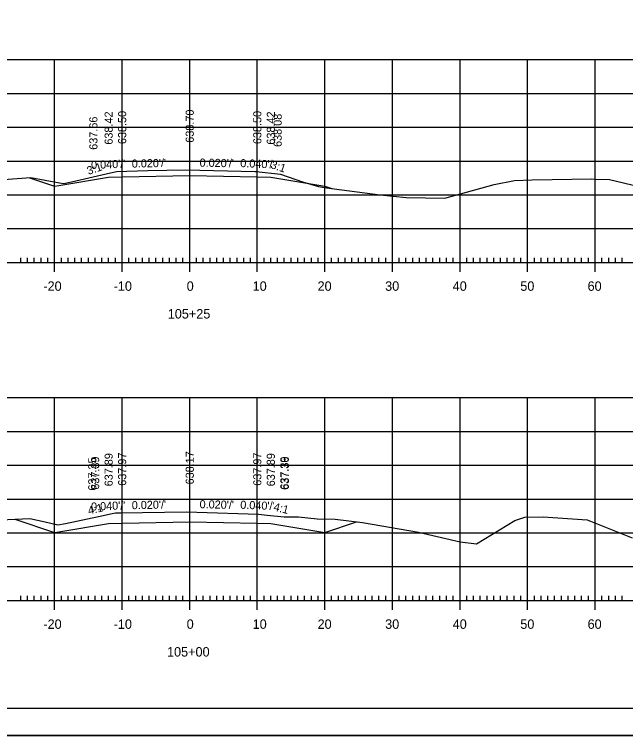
# Model space of a CAD drawing. Extents: x 1381471 to 1382703, y 370300 to 371487.
# Drawn here: x 1382110.7 to 1382201.1, y 371273.8 to 371380.5 of the extents above; entities that cross this region are included whole.
import ezdxf

# ---------------------------------------------------------------- set-up
doc = ezdxf.new("R2010")
doc.units = 0
doc.layers.add('Level 26', color=7, linetype='Continuous')
doc.layers.add('Level 45', color=7, linetype='Continuous')

msp = doc.modelspace()

# ---------------------------------------------------------------- linework, layer by layer
at = {"layer": 'Level 26'}
for points in [[(1382112.91, 371356.32), (1382116.61, 371355.09), (1382117.23, 371355.19), (1382124.61, 371356.42), (1382126.61, 371356.46), (1382136.61, 371356.66), (1382146.61, 371356.46), (1382148.61, 371356.42), (1382156, 371355.19), (1382156.61, 371355.09), (1382157.66, 371354.74)], [(1382110.71, 371305.84), (1382116.61, 371303.87), (1382117.23, 371303.97), (1382124.61, 371305.2), (1382126.61, 371305.24), (1382136.61, 371305.44), (1382146.61, 371305.24), (1382148.61, 371305.2), (1382156, 371303.97), (1382156.61, 371303.87), (1382161.27, 371305.42)]]:
    msp.add_lwpolyline(points, dxfattribs=at)
at = {"layer": 'Level 45'}
for p, q in [((1381996.61, 371373.8), (1382276.61, 371373.8)), ((1382116.61, 371343.8), (1382116.61, 371373.8)), ((1382126.61, 371343.8), (1382126.61, 371373.8)), ((1382136.61, 371343.8), (1382136.61, 371373.8)), ((1382146.61, 371343.8), (1382146.61, 371373.8)), ((1382156.61, 371343.8), (1382156.61, 371373.8)), ((1382166.61, 371343.8), (1382166.61, 371373.8)), ((1382176.61, 371343.8), (1382176.61, 371373.8)), ((1382186.61, 371343.8), (1382186.61, 371373.8)), ((1382196.61, 371343.8), (1382196.61, 371373.8)), ((1381996.61, 371368.8), (1382276.61, 371368.8)), ((1381996.61, 371363.8), (1382276.61, 371363.8)), ((1381996.61, 371358.8), (1382276.61, 371358.8)), ((1381996.61, 371353.8), (1382276.61, 371353.8)), ((1381996.61, 371348.8), (1382276.61, 371348.8)), ((1382116.61, 371342.4), (1382116.61, 371345.2)), ((1382126.61, 371342.4), (1382126.61, 371345.2)), ((1382136.61, 371342.4), (1382136.61, 371345.2)), ((1382146.61, 371342.4), (1382146.61, 371345.2)), ((1382156.61, 371342.4), (1382156.61, 371345.2)), ((1382166.61, 371342.4), (1382166.61, 371345.2)), ((1382176.61, 371342.4), (1382176.61, 371345.2)), ((1382186.61, 371342.4), (1382186.61, 371345.2)), ((1382196.61, 371342.4), (1382196.61, 371345.2)), ((1382111.61, 371343.8), (1382111.61, 371344.5)), ((1382112.61, 371343.8), (1382112.61, 371344.5)), ((1382113.61, 371343.8), (1382113.61, 371344.5)), ((1382114.61, 371343.8), (1382114.61, 371344.5)), ((1382115.61, 371343.8), (1382115.61, 371344.5)), ((1382117.61, 371343.8), (1382117.61, 371344.5)), ((1382118.61, 371343.8), (1382118.61, 371344.5)), ((1382119.61, 371343.8), (1382119.61, 371344.5)), ((1382120.61, 371343.8), (1382120.61, 371344.5)), ((1382121.61, 371343.8), (1382121.61, 371344.5)), ((1382122.61, 371343.8), (1382122.61, 371344.5)), ((1382123.61, 371343.8), (1382123.61, 371344.5)), ((1382124.61, 371343.8), (1382124.61, 371344.5)), ((1382125.61, 371343.8), (1382125.61, 371344.5)), ((1382127.61, 371343.8), (1382127.61, 371344.5)), ((1382128.61, 371343.8), (1382128.61, 371344.5)), ((1382129.61, 371343.8), (1382129.61, 371344.5)), ((1382130.61, 371343.8), (1382130.61, 371344.5)), ((1382131.61, 371343.8), (1382131.61, 371344.5)), ((1382132.61, 371343.8), (1382132.61, 371344.5)), ((1382133.61, 371343.8), (1382133.61, 371344.5)), ((1382134.61, 371343.8), (1382134.61, 371344.5)), ((1382135.61, 371343.8), (1382135.61, 371344.5)), ((1382137.61, 371343.8), (1382137.61, 371344.5)), ((1382138.61, 371343.8), (1382138.61, 371344.5)), ((1382139.61, 371343.8), (1382139.61, 371344.5)), ((1382140.61, 371343.8), (1382140.61, 371344.5)), ((1382141.61, 371343.8), (1382141.61, 371344.5)), ((1382142.61, 371343.8), (1382142.61, 371344.5)), ((1382143.61, 371343.8), (1382143.61, 371344.5)), ((1382144.61, 371343.8), (1382144.61, 371344.5)), ((1382145.61, 371343.8), (1382145.61, 371344.5)), ((1382147.61, 371343.8), (1382147.61, 371344.5)), ((1382148.61, 371343.8), (1382148.61, 371344.5)), ((1382149.61, 371343.8), (1382149.61, 371344.5)), ((1382150.61, 371343.8), (1382150.61, 371344.5)), ((1382151.61, 371343.8), (1382151.61, 371344.5)), ((1382152.61, 371343.8), (1382152.61, 371344.5)), ((1382153.61, 371343.8), (1382153.61, 371344.5)), ((1382154.61, 371343.8), (1382154.61, 371344.5)), ((1382155.61, 371343.8), (1382155.61, 371344.5)), ((1382157.61, 371343.8), (1382157.61, 371344.5)), ((1382158.61, 371343.8), (1382158.61, 371344.5)), ((1382159.61, 371343.8), (1382159.61, 371344.5)), ((1382160.61, 371343.8), (1382160.61, 371344.5)), ((1382161.61, 371343.8), (1382161.61, 371344.5)), ((1382162.61, 371343.8), (1382162.61, 371344.5)), ((1382163.61, 371343.8), (1382163.61, 371344.5)), ((1382164.61, 371343.8), (1382164.61, 371344.5)), ((1382165.61, 371343.8), (1382165.61, 371344.5)), ((1382167.61, 371343.8), (1382167.61, 371344.5)), ((1382168.61, 371343.8), (1382168.61, 371344.5)), ((1382169.61, 371343.8), (1382169.61, 371344.5)), ((1382170.61, 371343.8), (1382170.61, 371344.5)), ((1382171.61, 371343.8), (1382171.61, 371344.5)), ((1382172.61, 371343.8), (1382172.61, 371344.5)), ((1382173.61, 371343.8), (1382173.61, 371344.5)), ((1382174.61, 371343.8), (1382174.61, 371344.5)), ((1382175.61, 371343.8), (1382175.61, 371344.5)), ((1382177.61, 371343.8), (1382177.61, 371344.5)), ((1382178.61, 371343.8), (1382178.61, 371344.5)), ((1382179.61, 371343.8), (1382179.61, 371344.5)), ((1382180.61, 371343.8), (1382180.61, 371344.5)), ((1382181.61, 371343.8), (1382181.61, 371344.5)), ((1382182.61, 371343.8), (1382182.61, 371344.5)), ((1382183.61, 371343.8), (1382183.61, 371344.5)), ((1382184.61, 371343.8), (1382184.61, 371344.5)), ((1382185.61, 371343.8), (1382185.61, 371344.5)), ((1382187.61, 371343.8), (1382187.61, 371344.5)), ((1382188.61, 371343.8), (1382188.61, 371344.5)), ((1382189.61, 371343.8), (1382189.61, 371344.5)), ((1382190.61, 371343.8), (1382190.61, 371344.5)), ((1382191.61, 371343.8), (1382191.61, 371344.5)), ((1382192.61, 371343.8), (1382192.61, 371344.5)), ((1382193.61, 371343.8), (1382193.61, 371344.5)), ((1382194.61, 371343.8), (1382194.61, 371344.5)), ((1382195.61, 371343.8), (1382195.61, 371344.5)), ((1382197.61, 371343.8), (1382197.61, 371344.5)), ((1382198.61, 371343.8), (1382198.61, 371344.5)), ((1382199.61, 371343.8), (1382199.61, 371344.5)), ((1382200.61, 371343.8), (1382200.61, 371344.5)), ((1381996.61, 371343.8), (1382276.61, 371343.8)), ((1381996.61, 371343.8), (1382276.61, 371343.8)), ((1381996.61, 371323.8), (1382276.61, 371323.8)), ((1382116.61, 371293.8), (1382116.61, 371323.8)), ((1382126.61, 371293.8), (1382126.61, 371323.8)), ((1382136.61, 371293.8), (1382136.61, 371323.8)), ((1382146.61, 371293.8), (1382146.61, 371323.8)), ((1382156.61, 371293.8), (1382156.61, 371323.8)), ((1382166.61, 371293.8), (1382166.61, 371323.8)), ((1382176.61, 371293.8), (1382176.61, 371323.8)), ((1382186.61, 371293.8), (1382186.61, 371323.8)), ((1382196.61, 371293.8), (1382196.61, 371323.8)), ((1381996.61, 371318.8), (1382276.61, 371318.8)), ((1381996.61, 371313.8), (1382276.61, 371313.8)), ((1381996.61, 371308.8), (1382276.61, 371308.8)), ((1381996.61, 371303.8), (1382276.61, 371303.8)), ((1381996.61, 371298.8), (1382276.61, 371298.8)), ((1382116.61, 371292.4), (1382116.61, 371295.2)), ((1382126.61, 371292.4), (1382126.61, 371295.2)), ((1382136.61, 371292.4), (1382136.61, 371295.2)), ((1382146.61, 371292.4), (1382146.61, 371295.2)), ((1382156.61, 371292.4), (1382156.61, 371295.2)), ((1382166.61, 371292.4), (1382166.61, 371295.2)), ((1382176.61, 371292.4), (1382176.61, 371295.2)), ((1382186.61, 371292.4), (1382186.61, 371295.2)), ((1382196.61, 371292.4), (1382196.61, 371295.2)), ((1382111.61, 371293.8), (1382111.61, 371294.5)), ((1382112.61, 371293.8), (1382112.61, 371294.5)), ((1382113.61, 371293.8), (1382113.61, 371294.5)), ((1382114.61, 371293.8), (1382114.61, 371294.5)), ((1382115.61, 371293.8), (1382115.61, 371294.5)), ((1382117.61, 371293.8), (1382117.61, 371294.5)), ((1382118.61, 371293.8), (1382118.61, 371294.5)), ((1382119.61, 371293.8), (1382119.61, 371294.5)), ((1382120.61, 371293.8), (1382120.61, 371294.5)), ((1382121.61, 371293.8), (1382121.61, 371294.5)), ((1382122.61, 371293.8), (1382122.61, 371294.5)), ((1382123.61, 371293.8), (1382123.61, 371294.5)), ((1382124.61, 371293.8), (1382124.61, 371294.5)), ((1382125.61, 371293.8), (1382125.61, 371294.5)), ((1382127.61, 371293.8), (1382127.61, 371294.5)), ((1382128.61, 371293.8), (1382128.61, 371294.5)), ((1382129.61, 371293.8), (1382129.61, 371294.5)), ((1382130.61, 371293.8), (1382130.61, 371294.5)), ((1382131.61, 371293.8), (1382131.61, 371294.5)), ((1382132.61, 371293.8), (1382132.61, 371294.5)), ((1382133.61, 371293.8), (1382133.61, 371294.5)), ((1382134.61, 371293.8), (1382134.61, 371294.5)), ((1382135.61, 371293.8), (1382135.61, 371294.5)), ((1382137.61, 371293.8), (1382137.61, 371294.5)), ((1382138.61, 371293.8), (1382138.61, 371294.5)), ((1382139.61, 371293.8), (1382139.61, 371294.5)), ((1382140.61, 371293.8), (1382140.61, 371294.5)), ((1382141.61, 371293.8), (1382141.61, 371294.5)), ((1382142.61, 371293.8), (1382142.61, 371294.5)), ((1382143.61, 371293.8), (1382143.61, 371294.5)), ((1382144.61, 371293.8), (1382144.61, 371294.5)), ((1382145.61, 371293.8), (1382145.61, 371294.5)), ((1382147.61, 371293.8), (1382147.61, 371294.5)), ((1382148.61, 371293.8), (1382148.61, 371294.5)), ((1382149.61, 371293.8), (1382149.61, 371294.5)), ((1382150.61, 371293.8), (1382150.61, 371294.5)), ((1382151.61, 371293.8), (1382151.61, 371294.5)), ((1382152.61, 371293.8), (1382152.61, 371294.5)), ((1382153.61, 371293.8), (1382153.61, 371294.5)), ((1382154.61, 371293.8), (1382154.61, 371294.5)), ((1382155.61, 371293.8), (1382155.61, 371294.5)), ((1382157.61, 371293.8), (1382157.61, 371294.5)), ((1382158.61, 371293.8), (1382158.61, 371294.5)), ((1382159.61, 371293.8), (1382159.61, 371294.5)), ((1382160.61, 371293.8), (1382160.61, 371294.5)), ((1382161.61, 371293.8), (1382161.61, 371294.5)), ((1382162.61, 371293.8), (1382162.61, 371294.5)), ((1382163.61, 371293.8), (1382163.61, 371294.5)), ((1382164.61, 371293.8), (1382164.61, 371294.5)), ((1382165.61, 371293.8), (1382165.61, 371294.5)), ((1382167.61, 371293.8), (1382167.61, 371294.5)), ((1382168.61, 371293.8), (1382168.61, 371294.5)), ((1382169.61, 371293.8), (1382169.61, 371294.5)), ((1382170.61, 371293.8), (1382170.61, 371294.5)), ((1382171.61, 371293.8), (1382171.61, 371294.5)), ((1382172.61, 371293.8), (1382172.61, 371294.5)), ((1382173.61, 371293.8), (1382173.61, 371294.5)), ((1382174.61, 371293.8), (1382174.61, 371294.5)), ((1382175.61, 371293.8), (1382175.61, 371294.5)), ((1382177.61, 371293.8), (1382177.61, 371294.5)), ((1382178.61, 371293.8), (1382178.61, 371294.5)), ((1382179.61, 371293.8), (1382179.61, 371294.5)), ((1382180.61, 371293.8), (1382180.61, 371294.5)), ((1382181.61, 371293.8), (1382181.61, 371294.5)), ((1382182.61, 371293.8), (1382182.61, 371294.5)), ((1382183.61, 371293.8), (1382183.61, 371294.5)), ((1382184.61, 371293.8), (1382184.61, 371294.5)), ((1382185.61, 371293.8), (1382185.61, 371294.5)), ((1382187.61, 371293.8), (1382187.61, 371294.5)), ((1382188.61, 371293.8), (1382188.61, 371294.5)), ((1382189.61, 371293.8), (1382189.61, 371294.5)), ((1382190.61, 371293.8), (1382190.61, 371294.5)), ((1382191.61, 371293.8), (1382191.61, 371294.5)), ((1382192.61, 371293.8), (1382192.61, 371294.5)), ((1382193.61, 371293.8), (1382193.61, 371294.5)), ((1382194.61, 371293.8), (1382194.61, 371294.5)), ((1382195.61, 371293.8), (1382195.61, 371294.5)), ((1382197.61, 371293.8), (1382197.61, 371294.5)), ((1382198.61, 371293.8), (1382198.61, 371294.5)), ((1382199.61, 371293.8), (1382199.61, 371294.5)), ((1382200.61, 371293.8), (1382200.61, 371294.5)), ((1381996.61, 371293.8), (1382276.61, 371293.8)), ((1381996.61, 371293.8), (1382276.61, 371293.8)), ((1382294.79, 371277.8), (1381978.61, 371277.8)), ((1381966.21, 371273.82), (1382299.55, 371273.82))]:
    msp.add_line(p, q, dxfattribs=at)
for points in [[(1381966.21, 371487.15), (1382299.55, 371487.15), (1382299.55, 371273.81), (1381966.21, 371273.81)], [(1382212.53, 371483.26), (1382232.15, 371483.26), (1382232.15, 371473.38), (1382248.27, 371473.38), (1382271.46, 371473.38), (1382271.46, 371449.04), (1382294.79, 371449.04), (1382294.79, 371277.8), (1381978.61, 371277.8), (1381978.61, 371483.26)]]:
    msp.add_lwpolyline(points, close=True, dxfattribs=at)
for points in [[(1382100.9, 371355.48), (1382113.11, 371356.34), (1382117.35, 371355.57), (1382117.96, 371355.46), (1382119.13, 371355.72), (1382123.59, 371356.74), (1382124.23, 371356.9), (1382125.77, 371357.27), (1382130.4, 371357.39), (1382136.03, 371357.51), (1382146.29, 371357.24), (1382146.37, 371357.23), (1382146.43, 371357.23), (1382150.03, 371356.83), (1382153.32, 371355.72), (1382155.69, 371355.01), (1382156.84, 371354.85), (1382164.79, 371353.81), (1382168.65, 371353.41), (1382174.34, 371353.28), (1382181.64, 371355.33), (1382184.65, 371355.91), (1382187.27, 371356), (1382196.12, 371356.14), (1382196.63, 371356.12), (1382198.74, 371356.05), (1382211.78, 371352.96)], [(1382104.21, 371305.54), (1382112.95, 371305.94), (1382115.22, 371305.44), (1382117.1, 371305), (1382118.24, 371305.2), (1382123.09, 371306.24), (1382125.15, 371306.67), (1382125.61, 371306.75), (1382126.4, 371306.77), (1382136.07, 371306.91), (1382137.67, 371306.86), (1382146.79, 371306.54), (1382148.06, 371306.42), (1382150.57, 371306.16), (1382152.72, 371306.18), (1382155.47, 371305.85), (1382158.14, 371305.81), (1382162.16, 371305.31), (1382170.46, 371303.92), (1382176.61, 371302.47), (1382179.04, 371302.19), (1382184.71, 371305.63), (1382186.2, 371306.14), (1382188.91, 371306.19), (1382195.44, 371305.71), (1382202.11, 371303.06)]]:
    msp.add_lwpolyline(points, dxfattribs=at)

# ---------------------------------------------------------------- texts
for s, rotation, p in [('637.66', 90, (1382122.95, 371360.46)), ('638.42', 90, (1382125.21, 371361.22)), ('638.50', 90, (1382127.21, 371361.3)), ('638.70', 90, (1382137.21, 371361.5)), ('638.50', 90, (1382147.21, 371361.3)), ('638.42', 90, (1382149.21, 371361.22)), ('638.08', 90, (1382150.22, 371360.88)), ("0.040'/'", 2.2906, (1382122.03, 371357.61)), ("0.020'/'", 1.1458, (1382128.04, 371357.82)), ("0.020'/'", 358.8542, (1382138.06, 371357.97)), ("0.040'/'", 357.7094, (1382144.07, 371357.9)), ('3:1', 18.4349, (1382121.63, 371356.74)), ('3:1', 341.5651, (1382148.49, 371357.78)), ('637.89', 90, (1382125.21, 371310.68)), ('637.97', 90, (1382127.21, 371310.76)), ('638.17', 90, (1382137.21, 371310.96)), ('637.97', 90, (1382147.21, 371310.76)), ('637.89', 90, (1382149.21, 371310.68)), ('637.25', 90, (1382122.79, 371310.04)), ('637.39', 90, (1382123.21, 371310.18)), ('637.39', 90, (1382151.21, 371310.18)), ('637.36', 90, (1382151.29, 371310.16)), ('4:1', 14.0362, (1382121.7, 371306.47)), ("0.040'/'", 2.2906, (1382122.03, 371307.08)), ("0.020'/'", 1.1458, (1382128.04, 371307.29)), ("0.020'/'", 358.8542, (1382138.06, 371307.44)), ("0.040'/'", 357.7094, (1382144.07, 371307.37)), ('4:1', 345.9638, (1382148.93, 371307.12))]:
    msp.add_text(s, height=1.2, rotation=rotation, dxfattribs=at).set_placement(p)
for s, p in [('-20', (1382114.95, 371339.6)), ('-10', (1382125.35, 371339.6)), ('0', (1382136.16, 371339.6)), ('10', (1382145.92, 371339.6)), ('20', (1382155.53, 371339.6)), ('30', (1382165.53, 371339.6)), ('40', (1382175.53, 371339.6)), ('50', (1382185.53, 371339.6)), ('60', (1382195.49, 371339.6)), ('105+25', (1382133.36, 371335.5)), ('-20', (1382114.95, 371289.6)), ('-10', (1382125.35, 371289.6)), ('0', (1382136.16, 371289.6)), ('10', (1382145.92, 371289.6)), ('20', (1382155.53, 371289.6)), ('30', (1382165.53, 371289.6)), ('40', (1382175.53, 371289.6)), ('50', (1382185.53, 371289.6)), ('60', (1382195.49, 371289.6)), ('105+00', (1382133.25, 371285.5))]:
    msp.add_text(s, height=1.4, dxfattribs=at).set_placement(p)

doc.saveas('drawing.dxf')
